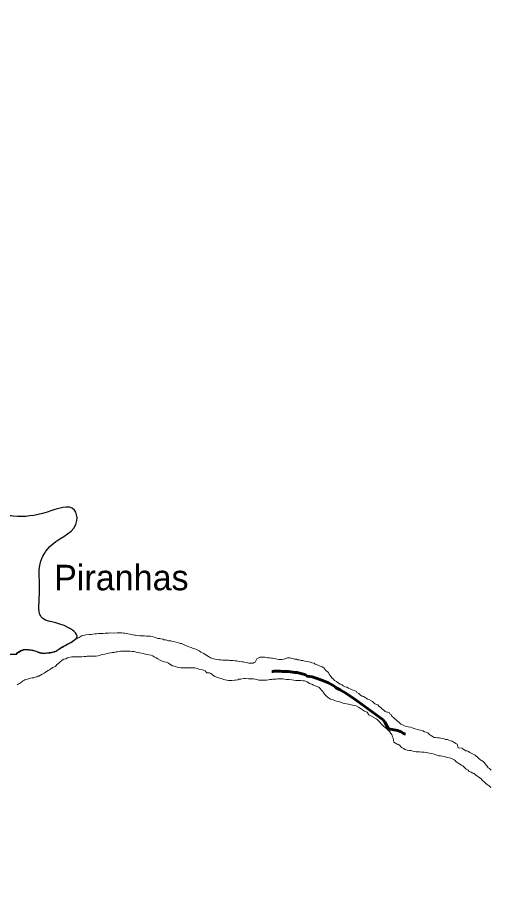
# Model space of a CAD drawing. Extents: x -1643653 to 4543381, y 1624270 to 13878484.
# Drawn here: x 635696 to 644975, y 8930690 to 8948035 of the extents above; entities that cross this region are included whole.
import ezdxf

# ---------------------------------------------------------------- set-up
doc = ezdxf.new("R2010")
doc.units = 0
doc.header["$LTSCALE"] = 200
doc.linetypes.add('LONG_DASH_SHORT_DASH', pattern=[9.9, 6, -1.2, 1.5, -1.2])
for name, color, linetype, lineweight in [('21', 7, 'Continuous', 25), ('25', 7, 'Continuous', 13), ('60', 7, 'Continuous', 13), ('7', 7, 'LONG_DASH_SHORT_DASH', 60), ('9', 7, 'Continuous', 90)]:
    doc.layers.add(name, color=color, linetype=linetype, lineweight=lineweight)
doc.layers.add('41', color=7, linetype='Continuous')

msp = doc.modelspace()

# ---------------------------------------------------------------- linework, layer by layer
at = {"layer": '21'}
msp.add_spline([(635677.5, 8935542.3), (635110.6, 8935620.5), (634836.9, 8935855.3), (634709.8, 8936099.8), (634846.6, 8936275.8), (634973.7, 8936735.4), (635032.4, 8937263.6), (634739.1, 8937449.4), (634426.3, 8937517.8), (634700, 8937928.6), (634700, 8938261.1), (634533.8, 8938671.9), (634641.4, 8938906.6), (634768.4, 8938867.5), (634866.2, 8938740.3), (635130.1, 8938750.1), (635188.8, 8938564.3), (635325.6, 8938329.6), (635609.1, 8938251.3), (636273.8, 8938329.6), (636811.4, 8938368.7), (636860.3, 8938163.3), (636371.5, 8937693.9), (636136.9, 8937312.5), (636127.2, 8936784.3), (636156.5, 8936275.8), (636694.1, 8936060.6), (636850.5, 8935855.3), (636821.3, 8935831.4), (636756.6, 8935782.4), (636679.7, 8935742.2), (636611.5, 8935703.8), (636571.3, 8935684.5), (636504.8, 8935639.1), (636420.9, 8935593.6), (636337, 8935576.1), (636239.1, 8935562.1), (636151.7, 8935569.1), (636071.2, 8935593.6), (635990.8, 8935618.1), (635878.9, 8935632.1), (635826.5, 8935633.8), (635795, 8935628.6), (635758.3, 8935612.8), (635712.8, 8935584.8), (635680.9, 8935555.9), (635677.5, 8935542.3)], degree=3, dxfattribs=at)
at = {"layer": '25'}
for points in [[(635685.7, 8935554.4), (635710.8, 8935574.3), (635733.4, 8935581.6), (635756.1, 8935601.5), (635776.2, 8935611.4), (635796.2, 8935616.2), (635818.8, 8935626.1), (635848.8, 8935625.9), (635868.8, 8935625.8), (635908.8, 8935623), (635941.3, 8935617.8), (635973.8, 8935612.6), (636006.2, 8935604.8), (636036.2, 8935597.1), (636073.6, 8935586.9), (636096, 8935574.2), (636130.9, 8935559), (636165.9, 8935556.2), (636185.9, 8935556.1), (636205.9, 8935556), (636243.4, 8935555.7), (636263.5, 8935558.1), (636283.5, 8935557.9), (636303.5, 8935560.3), (636326, 8935562.7), (636346.1, 8935565), (636366.1, 8935569.9), (636398.7, 8935579.7), (636418.7, 8935582.1), (636456.4, 8935599.4), (636479, 8935616.7), (636519.2, 8935636.5), (636539.3, 8935653.9), (636579.5, 8935671.2), (636602.1, 8935691), (636642.3, 8935710.8), (636675, 8935730.6), (636712.6, 8935747.9), (636737.7, 8935762.7), (636770.4, 8935785.1), (636793.1, 8935802.4), (636835.8, 8935834.7), (636863.5, 8935852), (636906.1, 8935869.3), (636941.3, 8935891.6), (636964, 8935908.9), (637009, 8935916.2), (637036.6, 8935923.5), (637099.2, 8935928.1), (637136.7, 8935930.3), (637169.2, 8935935.1), (637214.3, 8935937.3), (637241.8, 8935942.2), (637284.4, 8935946.9), (637304.4, 8935946.8), (637351.9, 8935946.4), (637374.4, 8935948.8), (637412, 8935951.1), (637437, 8935953.4), (637479.5, 8935955.6), (637524.6, 8935960.3), (637584.6, 8935954.9), (637652.2, 8935962), (637672.2, 8935961.8), (637694.7, 8935961.7), (637719.7, 8935961.5), (637742.2, 8935958.9), (637777.1, 8935953.6), (637799.7, 8935953.5), (637824.6, 8935945.8), (637859.6, 8935938.1), (637897, 8935932.8), (637922, 8935927.6), (637959.5, 8935922.4), (637989.5, 8935917.2), (638012, 8935914.5)], [(638012, 8935914.5), (638051.9, 8935909.3), (638091.9, 8935904), (638116.9, 8935901.3), (638154.4, 8935901.1), (638186.9, 8935898.3), (638226.9, 8935895.6), (638259.4, 8935895.4), (638281.9, 8935895.2), (638301.9, 8935895.1), (638341.9, 8935887.3), (638376.8, 8935874.6), (638414.2, 8935861.8), (638449.2, 8935851.6), (638486.6, 8935846.3), (638509.1, 8935841.1), (638544.1, 8935835.9), (638566.5, 8935825.7), (638599, 8935820.5), (638621.5, 8935812.9), (638663.9, 8935805.1), (638701.4, 8935799.8), (638721.4, 8935799.7), (638761.3, 8935786.9), (638808.8, 8935779.1), (638851.2, 8935763.8), (638891.1, 8935753.5), (638913.6, 8935750.8), (638951, 8935733.1), (638978.4, 8935717.9), (639020.8, 8935700.1), (639058.2, 8935684.8), (639103.1, 8935669.5), (639130.5, 8935656.8), (639170.4, 8935646.5), (639195.4, 8935636.3), (639232.7, 8935618.6), (639260.2, 8935605.8), (639290, 8935583.1), (639327.4, 8935565.3), (639349.8, 8935555.2), (639374.7, 8935535), (639412, 8935512.2), (639444.4, 8935494.5), (639481.7, 8935471.7), (639519.2, 8935458.9), (639544.1, 8935451.3), (639576.6, 8935443.5), (639614, 8935438.3), (639646.5, 8935433.1), (639686.5, 8935427.8), (639719, 8935425.1), (639739, 8935424.9), (639761.5, 8935424.8), (639784, 8935422.1), (639814, 8935421.9), (639834, 8935421.8), (639856.5, 8935419.1), (639889, 8935416.4), (639921.5, 8935413.7), (639956.5, 8935413.5), (639991.5, 8935408.2), (640021.5, 8935405.5), (640053.9, 8935400.3), (640093.9, 8935392.5), (640126.4, 8935389.8), (640148.9, 8935384.7), (640183.8, 8935376.9), (640233.7, 8935364.2), (640316.3, 8935366), (640339.2, 8935375.1), (640361.5, 8935385.8), (640394.5, 8935450.6), (640447.2, 8935480.3), (640467.3, 8935485.2), (640487.3, 8935485.1), (640514.8, 8935482.4), (640549.8, 8935479.7), (640572.2, 8935474.5), (640607.2, 8935471.8), (640639.7, 8935466.5), (640677.2, 8935463.8), (640699.7, 8935461.1), (640732.2, 8935455.9), (640767.1, 8935450.7), (640789.6, 8935440.5), (640822, 8935435.3), (640842.1, 8935435.2), (640864.6, 8935435), (640884.6, 8935434.9), (640947.2, 8935447), (640994.9, 8935466.7), (641014.9, 8935466.6), (641037.4, 8935466.4), (641067.3, 8935461.2), (641089.8, 8935453.6), (641132.3, 8935445.8), (641167.2, 8935440.5), (641189.7, 8935432.8), (641224.7, 8935427.6), (641259.6, 8935419.9)], [(638992.5, 8935272.2), (638970, 8935272.3), (638925, 8935272.6), (638897.5, 8935275.3), (638855, 8935278.1), (638825, 8935285.8), (638777.6, 8935303.6), (638737.7, 8935311.4), (638700.3, 8935331.7), (638658.1, 8935364.5), (638618.2, 8935382.3), (638573.2, 8935387.6), (638535.8, 8935402.8), (638495.9, 8935423.1), (638451.1, 8935451), (638413.8, 8935471.2), (638376.4, 8935489), (638351.5, 8935506.7), (638314.1, 8935522), (638274.1, 8935529.8), (638224.2, 8935537.6), (638161.8, 8935553), (638086.8, 8935568.6), (638059.4, 8935576.2), (638019.4, 8935581.5), (637982, 8935591.8), (637947, 8935594.5), (637907, 8935599.8), (637884.5, 8935599.9), (637847, 8935600.2), (637827, 8935600.3), (637792, 8935600.5), (637754.5, 8935600.8), (637714.4, 8935601.1), (637691.9, 8935596.2), (637654.3, 8935588.9), (637631.8, 8935584.1), (637591.7, 8935576.8), (637549.2, 8935574.6), (637524.1, 8935567.3), (637481.5, 8935560), (637461.5, 8935552.7), (637426.4, 8935547.9), (637406.4, 8935543), (637371.3, 8935535.7), (637336.2, 8935528.4), (637298.6, 8935516.2), (637278.5, 8935508.8), (637238.5, 8935504.1), (637215.9, 8935499.2), (637180.9, 8935499.4), (637135.9, 8935499.7), (637105.9, 8935499.9), (637063.4, 8935500.2), (637040.8, 8935497.9), (637000.8, 8935493.1), (636955.8, 8935490.9), (636930.8, 8935491.1), (636890.7, 8935488.8), (636868.2, 8935489), (636830.7, 8935489.2), (636810.7, 8935489.4), (636780.7, 8935489.6), (636760.7, 8935489.7), (636725.6, 8935484.9), (636693, 8935475.1), (636673, 8935467.8), (636640.3, 8935447.9), (636605.2, 8935443.2), (636567.6, 8935420.9), (636524.7, 8935381.1), (636499.6, 8935358.7), (636466.9, 8935336.4), (636436.6, 8935301.6), (636416.5, 8935294.2), (636378.9, 8935276.9), (636343.6, 8935244.6), (636323.5, 8935234.7), (636293.4, 8935219.9), (636260.8, 8935200.1), (636238.1, 8935180.2), (636215.5, 8935167.8), (636180.3, 8935148.1), (636142.7, 8935128.3), (636112.5, 8935110.9), (636092.5, 8935108.6), (636069.9, 8935098.7), (636037.3, 8935088.9), (636014.7, 8935079.1), (635982.2, 8935074.3), (635947.1, 8935067), (635912, 8935059.7), (635892, 8935052.3), (635859.4, 8935042.5), (635839.3, 8935037.7), (635816.7, 8935025.3), (635794.1, 8935010.4), (635773.9, 8934990.5), (635753.8, 8934975.6), (635731.2, 8934963.3), (635708.6, 8934950.9)], [(641259.6, 8935419.9), (641294.6, 8935414.6), (641334.5, 8935404.4), (641369.5, 8935399.1), (641409.5, 8935393.8), (641441.9, 8935383.6), (641474.3, 8935368.4), (641514.3, 8935363.1), (641536.7, 8935345.4), (641574.1, 8935330.2), (641596.6, 8935325), (641636.4, 8935307.2), (641673.8, 8935289.5), (641708.7, 8935271.7), (641748.3, 8935223.9), (641798.1, 8935183.5), (641812.8, 8935148.3), (641832.6, 8935125.7), (641842.5, 8935100.6), (641872.2, 8935067.8), (641894.6, 8935047.7), (641916.9, 8935022.5), (641954.2, 8935002.2), (641994, 8934971.9), (642028.9, 8934954.1), (642063.8, 8934936.4), (642086.2, 8934918.7), (642126, 8934898.4), (642161, 8934890.7), (642188.4, 8934873), (642225.8, 8934860.2), (642260.7, 8934842.4), (642283.1, 8934832.3), (642318, 8934819.5), (642340.5, 8934811.9), (642357.8, 8934791.7), (642395.2, 8934769), (642427.4, 8934736.2), (642462.3, 8934715.9), (642484.8, 8934708.3), (642517.1, 8934690.5), (642539.5, 8934675.4), (642561.9, 8934660.2), (642604.3, 8934642.4), (642661.6, 8934609.5), (642711.2, 8934564.1), (642766.1, 8934543.7), (642790.9, 8934513.5), (642825.8, 8934495.7), (642845.6, 8934470.6), (642875.5, 8934450.3), (642907.7, 8934417.6), (642942.6, 8934402.3), (642965.1, 8934402.2), (642987.6, 8934394.5), (643004.9, 8934366.9), (643027.3, 8934356.7), (643044.6, 8934324), (643084.3, 8934286.2), (643146.4, 8934233.2), (643183.7, 8934202.9), (643221, 8934167.7), (643253.4, 8934152.4), (643288.2, 8934132.2), (643323.2, 8934124.4), (643363.1, 8934114.1), (643405.6, 8934108.8), (643440.5, 8934096.1), (643477.9, 8934083.3), (643500.4, 8934075.7), (643542.8, 8934060.4), (643567.8, 8934055.2), (643602.8, 8934052.5), (643647.6, 8934034.7), (643685, 8934019.4), (643717.5, 8934009.2), (643749.9, 8933993.9), (643784.6, 8933958.6), (643814.5, 8933943.4), (643836.9, 8933925.7), (643871.7, 8933903), (643899.2, 8933902.8), (643936.7, 8933900.1), (643971.7, 8933897.3), (644004.2, 8933892.1), (644026.7, 8933884.4), (644066.6, 8933876.7), (644096.6, 8933868.9), (644136.6, 8933863.7), (644161.5, 8933856), (644196.4, 8933843.2), (644226.3, 8933830.5), (644263.7, 8933810.3), (644301.1, 8933790), (644323.4, 8933772.3), (644345.4, 8933699.6), (644415.4, 8933699.1), (644437.8, 8933683.9), (644460.2, 8933663.8), (644492.6, 8933646), (644522.5, 8933640.8)], [(642690, 8934297.2), (642645.2, 8934327.5), (642587.9, 8934347.9), (642556.4, 8934400.2), (642504.8, 8934424.3), (642466.9, 8934451.8), (642425.6, 8934475.9), (642384.3, 8934503.4), (642339.5, 8934524.1), (642294.8, 8934534.4), (642294.8, 8934534.4), (642246.6, 8934548.2), (642188.1, 8934561.9), (642151.8, 8934566.1), (642086.9, 8934579), (642032, 8934596.9), (641994.6, 8934612.2), (641952.2, 8934620), (641902.2, 8934635.3), (641874.9, 8934653.1), (641834.9, 8934658.3), (641800.1, 8934686.1), (641770.2, 8934701.3), (641755.4, 8934726.4), (641723.1, 8934756.7), (641698.3, 8934789.4), (641681, 8934817.1), (641663.7, 8934837.2), (641628.9, 8934872.5), (641609.1, 8934892.6), (641558.1, 8934912.8), (641506.5, 8934933.5), (641473.6, 8934950.3), (641426.3, 8934968.1), (641376.5, 8935001), (641329.1, 8935016.3), (641301.6, 8935019), (641254.1, 8935021.8), (641209.1, 8935024.7), (641159.1, 8935027.5), (641081.6, 8935035.5), (641021.6, 8935040.9), (640971.7, 8935046.2), (640936.7, 8935051.5), (640899.2, 8935054.2), (640864.2, 8935054.5), (640841.7, 8935054.6), (640806.6, 8935054.8), (640769.1, 8935052.6), (640744.1, 8935050.3), (640704, 8935048), (640684, 8935043.2), (640649, 8935040.9), (640621.4, 8935036.1), (640578.9, 8935033.8), (640543.8, 8935031.6), (640498.8, 8935031.8), (640471.3, 8935032), (640451.3, 8935032.2), (640431.3, 8935032.3), (640393.9, 8935042.6), (640358.9, 8935052.8), (640326.5, 8935058), (640229.1, 8935058.3), (640168.9, 8935061.6), (640141.4, 8935061.8), (640098.9, 8935059.5), (640076.3, 8935052.2), (640041.2, 8935047.4), (640016.2, 8935040.1), (639971.1, 8935032.8), (639951.1, 8935028), (639898.5, 8935025.8), (639856, 8935026.1), (639833.5, 8935026.2), (639801, 8935029), (639768.6, 8935039.2), (639738.6, 8935044.4), (639708.7, 8935054.6), (639686.2, 8935062.3), (639663.8, 8935072.4), (639628.9, 8935085.2), (639601.4, 8935090.4), (639564, 8935105.6), (639536.6, 8935120.8), (639511.7, 8935141), (639489.3, 8935158.7), (639464.5, 8935173.9), (639409.4, 8935171.8), (639379.8, 8935217), (639342.3, 8935227.3), (639317.4, 8935234.9), (639274.9, 8935242.7), (639240, 8935255.5), (639202.5, 8935263.2), (639177.6, 8935270.9), (639125.1, 8935271.3), (639090, 8935271.5), (639050, 8935271.8), (639030, 8935271.9), (638992.5, 8935272.2)], [(635708.6, 8934950.9), (635686, 8934941)], [(644987.3, 8932926.7), (644950, 8932954.5), (644912.7, 8932984.8), (644890.3, 8933002.5), (644855.6, 8933032.8), (644820.8, 8933063), (644798.5, 8933093.2), (644766.1, 8933113.5), (644746.3, 8933133.6), (644723.9, 8933148.8), (644691.5, 8933166.5), (644656.7, 8933196.8), (644634.3, 8933204.5), (644599.4, 8933224.7), (644559.5, 8933235), (644539.7, 8933262.7), (644499.8, 8933285.5), (644477.5, 8933310.6), (644432.8, 8933348.5), (644410.4, 8933363.7), (644375.5, 8933378.9), (644338.2, 8933406.7), (644305.8, 8933426.9), (644286, 8933457.1), (644263.6, 8933467.3), (644228.7, 8933485), (644198.8, 8933497.7), (644166.3, 8933505.5), (644143.9, 8933513.1), (644106.4, 8933520.9), (644066.5, 8933533.7), (644034, 8933538.9), (643996.6, 8933544.2), (643964.1, 8933546.9), (643926.6, 8933557.1), (643891.7, 8933569.9), (643851.8, 8933582.7), (643816.8, 8933590.4), (643779.4, 8933595.7), (643749.4, 8933603.4), (643716.9, 8933608.6), (643677, 8933616.4), (643654.5, 8933619), (643632, 8933619.2), (643587, 8933622), (643564.5, 8933624.6), (643542, 8933624.8), (643522, 8933624.9), (643487, 8933630.1), (643457, 8933637.8), (643417.1, 8933650.6), (643379.6, 8933653.4), (643342.1, 8933658.6), (643304.7, 8933668.9), (643269.8, 8933686.7), (643232.5, 8933706.9), (643212.7, 8933734.6), (643195.3, 8933754.7), (643170.4, 8933764.9), (643148, 8933777.6), (643078.2, 8933813.1), (643066.3, 8933890.8), (643056.5, 8933918.4), (643046.7, 8933941), (643039.3, 8933966.1), (643022, 8933986.2), (643004.7, 8934016.4), (642970, 8934051.7), (642947.6, 8934071.8), (642910.3, 8934099.6), (642880.5, 8934127.3), (642842.1, 8934169.7), (642842.1, 8934169.7), (642804.3, 8934207.6), (642755, 8934260.3), (642734.8, 8934269.3), (642690, 8934297.2)], [(644522.5, 8933640.8), (644547.4, 8933628.1), (644574.8, 8933612.9), (644614.7, 8933592.6), (644649.5, 8933569.9), (644674.5, 8933559.7), (644699.3, 8933537), (644721.7, 8933519.3), (644756.5, 8933489.1), (644786.3, 8933461.3), (644811.2, 8933453.6), (644841.1, 8933428.4), (644860.9, 8933408.2), (644875.7, 8933385.6), (644895.6, 8933363), (644915.4, 8933342.8), (644935.2, 8933312.6), (644957.6, 8933297.4), (644989.9, 8933267.2)]]:
    msp.add_lwpolyline(points, dxfattribs=at)
at = {"layer": '60', "lineweight": 25}
msp.add_spline([(814781, 9009175.5), (814787.2, 9009173.4), (814796.9, 9009173.4), (814799.4, 9009172.4), (814805.1, 9009174.5), (814805.6, 9009176.5), (814811.7, 9009179.5), (814811.7, 9009179.5), (814801.5, 9009181), (814790.7, 9009181.5), (814784.1, 9009183.1), (814777.4, 9009185.1), (814778.4, 9009175.5)], degree=3, dxfattribs=at)
at = {"layer": '7'}
for points in [[(641349.5, 8935138.5), (641279.6, 8935153.8), (641232.2, 8935166.6), (641182.2, 8935179.4), (641137.2, 8935182.1), (641014.8, 8935197.8), (640987.4, 8935200.4), (640937.4, 8935200.7), (640887.4, 8935203.5), (640847.4, 8935206.2), (640824.9, 8935206.3), (640794.9, 8935206.5), (640772.4, 8935206.6), (640732.4, 8935204.3), (640707.4, 8935199.4), (640683.2, 8935198.4)], [(643306.9, 8933971.4), (643271.7, 8933987.2), (643222, 8934017.5), (643154.6, 8934040.4), (642977.3, 8934076.3), (642905.7, 8934204.3), (642868.5, 8934249.6), (642368.5, 8934617.6), (642318.7, 8934652.9), (642216.7, 8934723.5), (642166.9, 8934758.8), (642137, 8934776.5), (642047.4, 8934827), (642025, 8934842.1), (641937.8, 8934885.1), (641922.9, 8934907.7), (641800.9, 8934978.4), (641648.8, 8935034.3), (641556.5, 8935072.3), (641479.2, 8935095.2), (641381.8, 8935110.8), (641349.5, 8935138.5)]]:
    msp.add_lwpolyline(points, dxfattribs=at)
at = {"layer": '9'}
msp.add_spline([(637260.6, 8972975.8), (641524.5, 8971056.2), (652526.1, 8965412.7), (653164.3, 8965062.8), (670790.5, 8953770.1), (686194, 8943929.9), (696283.3, 8937647.1)], degree=3, dxfattribs=at)

# ---------------------------------------------------------------- texts
at = {"layer": '41'}
msp.add_text('Piranhas', height=500, dxfattribs=at).set_placement((636412.8, 8936794.9))

doc.saveas('drawing.dxf')
